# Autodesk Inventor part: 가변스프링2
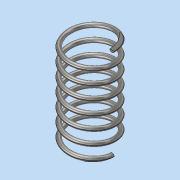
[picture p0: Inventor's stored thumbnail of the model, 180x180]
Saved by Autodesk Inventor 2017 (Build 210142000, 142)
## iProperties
Part Number: 가변스프링2
Material: 스테인레스 스틸
Document SubType Name: Modeling
Designer: MRC
Density: 8 g/cm^3
Appearance: 반연마
Mass: 10.9602 g
Surface Area: 27.6886 cm^2
Volume: 1.37003 cm^3
Author: MRC
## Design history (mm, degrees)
sketch "스케치1"
  geometry: L1 (0, 0)-(10, 0); L2 (10, 0)-(10, 41.411); L3 (10, 41.411)-(0, 41.411); L4 (0, 41.411)-(0, 0); C1 r 1 at (10, 0)
  constraints: 8 end point, 2 parallel, 1 centre point, 1 coincident, 1 horizontal, 1 perpendicular
  dimensions: "d1" = 41.4112 distance of L3.end L1.start (derived); "d2" = 20 diameter of L2 L4; "d3" = 2 diameter of C1
feature "코일1" sketch "스케치1" pitch "d4" = 10; turns "d6" = 7; dims "d5" = 41.4112 (= d1), "d7" = 0, angle "d8" = 90 deg, angle "d9" = 90 deg, "d10" = 0, "d11" = 0
sketch "스케치2"
  geometry: L1 (-20, 41.411)-(20, 41.411); L2 (20, 41.411)-(20, 0); L3 (20, 0)-(-20, 0); L4 (-20, 0)-(-20, 41.411); L5 (0, 41.411)-(0, 0) reference; 2 further points
  constraints: 8 end point, 2 midpoint, 2 parallel, 1 coincident, 1 horizontal, 1 perpendicular
  dimensions: "d12" = 40 distance between parallel lines of L4 L2
extrude "돌출1" sketch "스케치2" stored distance "d13" = 0; taper "d14" = 0 deg
node "솔리드1"
